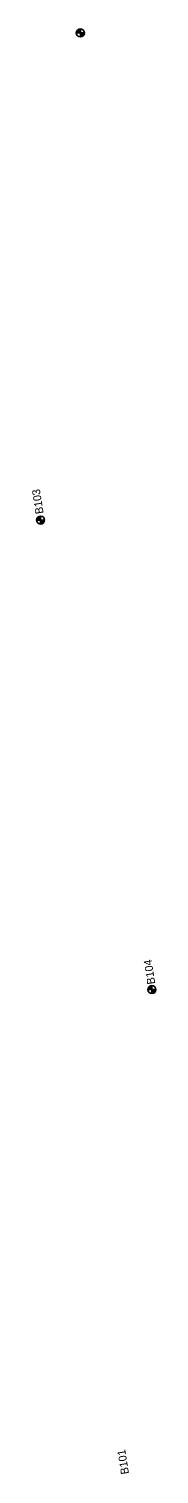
# Model space of a CAD drawing. Extents: x 335726 to 369746, y 119154 to 200788.
# Drawn here: x 355573 to 355728, y 184204 to 186010 of the extents above; entities that cross this region are included whole.
import ezdxf

# ---------------------------------------------------------------- set-up
doc = ezdxf.new("R2010")
doc.units = 0
for name, color, linetype in [('E_SOIL_BORE1 [KAPUR_CADDS_LEVELS]', 7, 'Continuous'), ('E_SOIL_BORE2 [KAPUR_CADDS_LEVELS]', 7, 'Continuous'), ('P_MARK', 7, 'Continuous')]:
    doc.layers.add(name, color=color, linetype=linetype)

msp = doc.modelspace()

# ---------------------------------------------------------------- linework, layer by layer
at = {"layer": 'P_MARK'}
for p, q in [((355628.3, 186004.9), (355638.3, 186004.9)), ((355633.3, 186009.9), (355633.3, 185999.9)), ((355583.7, 185401.1), (355583.7, 185391.1)), ((355578.7, 185396.1), (355588.7, 185396.1)), ((355717.7, 184809.3), (355727.7, 184809.3)), ((355722.7, 184814.3), (355722.7, 184804.3))]:
    msp.add_line(p, q, dxfattribs=at)
for centre in [(355633.3, 186004.9), (355583.7, 185396.1), (355722.7, 184809.3)]:
    msp.add_circle(centre, 5, dxfattribs=at)
for centre, radius, start, end in [((355633.3, 186004.9), 4.5, 89.9869, 179.9869), ((355633.3, 186004.9), 4, 89.9869, 179.9869), ((355633.3, 186004.9), 3.5, 89.9869, 179.9869), ((355633.3, 186004.9), 3, 89.9869, 179.9869), ((355633.3, 186004.9), 2.5, 89.9869, 179.9869), ((355633.3, 186004.9), 2, 89.9869, 179.9869), ((355633.3, 186004.9), 1.5, 89.9869, 179.9869), ((355633.3, 186004.9), 1, 89.9869, 179.9869), ((355633.3, 186004.9), 0.5, 89.9869, 179.9869), ((355633.3, 186004.9), 4.5, 269.9869, 359.9869), ((355633.3, 186004.9), 4, 269.9869, 359.9869), ((355633.3, 186004.9), 3.5, 269.9869, 359.9869), ((355633.3, 186004.9), 3, 269.9869, 359.9869), ((355633.3, 186004.9), 2.5, 269.9869, 359.9869), ((355633.3, 186004.9), 2, 269.9869, 359.9869), ((355633.3, 186004.9), 1.5, 269.9869, 359.9869), ((355633.3, 186004.9), 1, 269.9869, 359.9869), ((355633.3, 186004.9), 0.5, 269.9869, 359.9869), ((355583.7, 185396.1), 4.5, 89.9869, 179.9869), ((355583.7, 185396.1), 4, 89.9869, 179.9869), ((355583.7, 185396.1), 3.5, 89.9869, 179.9869), ((355583.7, 185396.1), 3, 89.9869, 179.9869), ((355583.7, 185396.1), 2.5, 89.9869, 179.9869), ((355583.7, 185396.1), 2, 89.9869, 179.9869), ((355583.7, 185396.1), 1.5, 89.9869, 179.9869), ((355583.7, 185396.1), 1, 89.9869, 179.9869), ((355583.7, 185396.1), 0.5, 89.9869, 179.9869), ((355583.7, 185396.1), 4.5, 269.9869, 359.9869), ((355583.7, 185396.1), 4, 269.9869, 359.9869), ((355583.7, 185396.1), 3.5, 269.9869, 359.9869), ((355583.7, 185396.1), 3, 269.9869, 359.9869), ((355583.7, 185396.1), 2.5, 269.9869, 359.9869), ((355583.7, 185396.1), 2, 269.9869, 359.9869), ((355583.7, 185396.1), 1.5, 269.9869, 359.9869), ((355583.7, 185396.1), 1, 269.9869, 359.9869), ((355583.7, 185396.1), 0.5, 269.9869, 359.9869), ((355722.7, 184809.3), 4.5, 89.9869, 179.9869), ((355722.7, 184809.3), 4, 89.9869, 179.9869), ((355722.7, 184809.3), 3.5, 89.9869, 179.9869), ((355722.7, 184809.3), 3, 89.9869, 179.9869), ((355722.7, 184809.3), 2.5, 89.9869, 179.9869), ((355722.7, 184809.3), 2, 89.9869, 179.9869), ((355722.7, 184809.3), 1.5, 89.9869, 179.9869), ((355722.7, 184809.3), 1, 89.9869, 179.9869), ((355722.7, 184809.3), 0.5, 89.9869, 179.9869), ((355722.7, 184809.3), 4.5, 269.9869, 359.9869), ((355722.7, 184809.3), 4, 269.9869, 359.9869), ((355722.7, 184809.3), 3.5, 269.9869, 359.9869), ((355722.7, 184809.3), 3, 269.9869, 359.9869), ((355722.7, 184809.3), 2.5, 269.9869, 359.9869), ((355722.7, 184809.3), 2, 269.9869, 359.9869), ((355722.7, 184809.3), 1.5, 269.9869, 359.9869), ((355722.7, 184809.3), 1, 269.9869, 359.9869), ((355722.7, 184809.3), 0.5, 269.9869, 359.9869)]:
    msp.add_arc(centre, radius, start, end, dxfattribs=at)

# ---------------------------------------------------------------- texts
at = {"layer": 'E_SOIL_BORE1 [KAPUR_CADDS_LEVELS]'}
for s, p in [('B104', (355727, 184816.6)), ('B101', (355694.1, 184204.3))]:
    msp.add_text(s, height=10, rotation=98.957, dxfattribs=at).set_placement(p)
at = {"layer": 'E_SOIL_BORE2 [KAPUR_CADDS_LEVELS]'}
msp.add_text('B103', height=10, rotation=98.957, dxfattribs=at).set_placement((355587.5, 185404.5))

doc.saveas('drawing.dxf')
